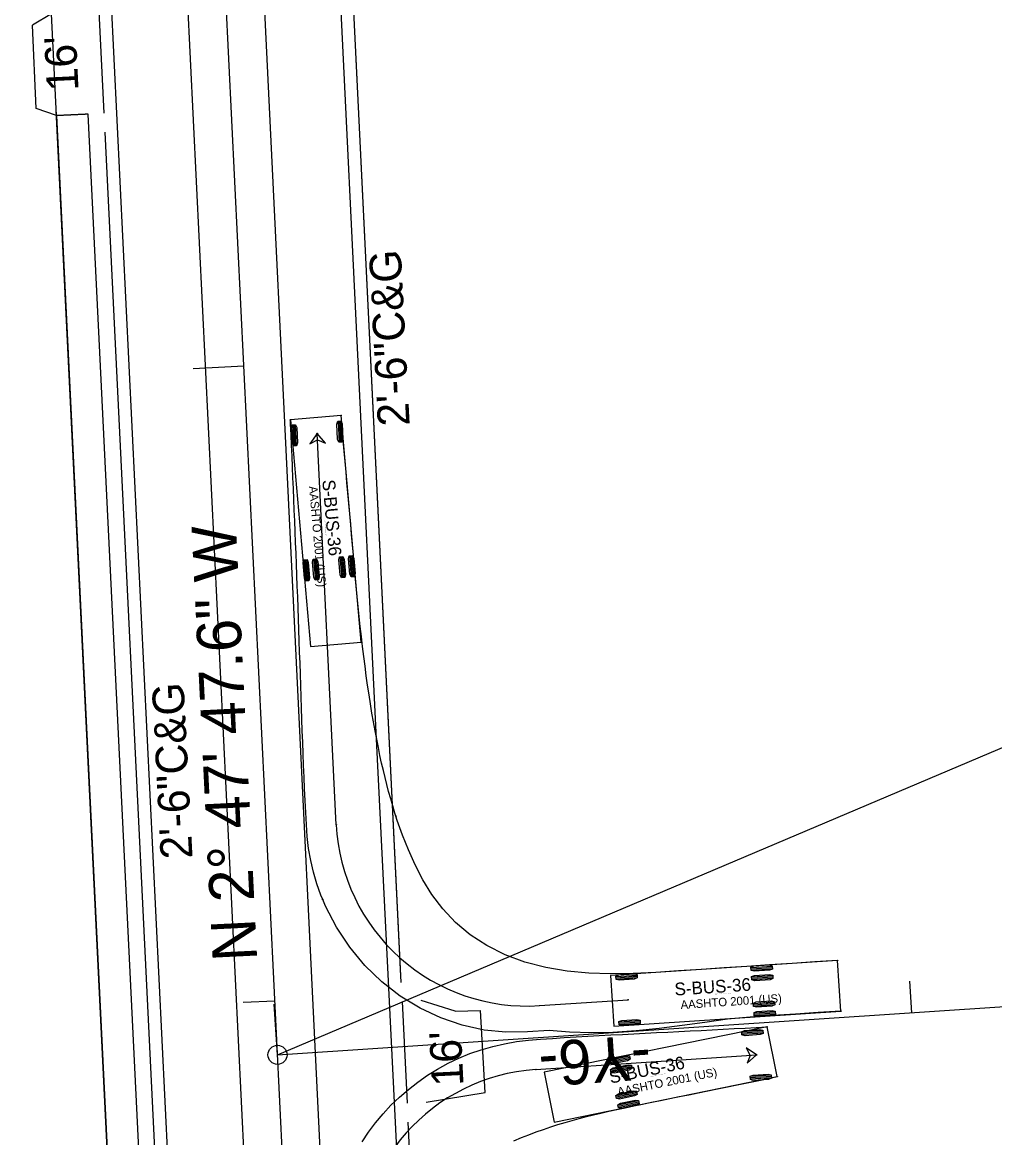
# Model space of a CAD drawing. Extents: x 2367848 to 2369479, y 800728 to 808616.
# Drawn here: x 2368775.2 to 2368928.2, y 804206 to 804381.5 of the extents above; entities that cross this region are included whole.
import ezdxf

# ---------------------------------------------------------------- set-up
doc = ezdxf.new("R2010")
doc.units = 0
for name, color, linetype in [('Prop AutoTurn Projected Path', 7, 'Continuous'), ('Prop AutoTurn Simulation', 7, 'Continuous'), ('Prop Conc 2ft 6in Curb and Gutter', 7, 'Continuous'), ('Prop Conc 4in Sidewalk', 7, 'Continuous'), ('Prop Conc Drive Radius Type', 7, 'Continuous'), ('Prop Conc Driveway', 7, 'Continuous'), ('Prop Dimension', 7, 'Continuous'), ('Prop EOT', 7, 'Continuous'), ('Prop Horizontal Alignment', 7, 'Continuous'), ('Prop Horizontal Alignment Direction Label', 7, 'Continuous'), ('Prop Horizontal Alignment Station Label', 7, 'Continuous'), ('Prop Horizontal Alignment Tick Large', 7, 'Continuous'), ('Prop Horizontal Alignment Tick Small', 7, 'Continuous'), ('Prop Lane Lines', 7, 'Continuous'), ('Prop Shade Light', 7, 'Continuous')]:
    doc.layers.add(name, color=color, linetype=linetype)

msp = doc.modelspace()

# ---------------------------------------------------------------- linework, layer by layer
at = {"layer": 'Prop AutoTurn Projected Path'}
for p, q in [((2368824.59, 804255.24), (2368821.59, 804316.8)), ((2368856.54, 804226.77), (2368870.5, 804227.69)), ((2368855.99, 804216.71), (2368890.72, 804219.01))]:
    msp.add_line(p, q, dxfattribs=at)
for centre, start, end in [((2368854.56, 804256.7), 182.7965, 273.7959), ((2368857.97, 804186.77), 93.7959, 182.7965)]:
    msp.add_arc(centre, 30, start, end, dxfattribs=at)
at = {"layer": 'Prop AutoTurn Simulation'}
for p, q in [((2368825.35, 804319.64), (2368817.38, 804318.94)), ((2368817.38, 804318.94), (2368820.52, 804283.28)), ((2368817.38, 804318.94), (2368817.38, 804318.94)), ((2368828.49, 804283.98), (2368825.35, 804319.64)), ((2368817.73, 804318.16), (2368817.89, 804314.83)), ((2368817.93, 804318.17), (2368818.1, 804314.84)), ((2368818.14, 804318.18), (2368818.3, 804314.85)), ((2368824.87, 804318.76), (2368825.03, 804315.43)), ((2368825.08, 804318.77), (2368825.24, 804315.44)), ((2368825.28, 804318.78), (2368825.45, 804315.45)), ((2368819.53, 804296.91), (2368819.82, 804293.59)), ((2368819.74, 804296.93), (2368820.03, 804293.61)), ((2368819.94, 804296.95), (2368820.24, 804293.63)), ((2368821.02, 804297.05), (2368821.32, 804293.72)), ((2368821.23, 804297.06), (2368821.52, 804293.74)), ((2368821.44, 804297.08), (2368821.73, 804293.76)), ((2368825.17, 804297.41), (2368825.47, 804294.09)), ((2368825.38, 804297.43), (2368825.67, 804294.11)), ((2368825.59, 804297.45), (2368825.88, 804294.13)), ((2368826.67, 804297.54), (2368826.96, 804294.22)), ((2368826.88, 804297.56), (2368827.17, 804294.24)), ((2368827.08, 804297.58), (2368827.38, 804294.26)), ((2368820.52, 804283.28), (2368828.49, 804283.98)), ((2368903.46, 804233.89), (2368867.74, 804231.52)), ((2368889.84, 804232.77), (2368893.16, 804232.99)), ((2368903.99, 804225.9), (2368903.46, 804233.89)), ((2368867.74, 804231.52), (2368868.27, 804223.53)), ((2368868.58, 804231.36), (2368871.91, 804231.58)), ((2368868.6, 804231.16), (2368871.92, 804231.38)), ((2368868.61, 804230.95), (2368871.94, 804231.17)), ((2368889.85, 804232.57), (2368893.18, 804232.79)), ((2368889.86, 804232.36), (2368893.19, 804232.58)), ((2368889.94, 804231.28), (2368893.26, 804231.5)), ((2368889.95, 804231.07), (2368893.28, 804231.29)), ((2368889.96, 804230.86), (2368893.29, 804231.08)), ((2368868.27, 804223.53), (2368903.99, 804225.9)), ((2368890.21, 804227.12), (2368893.54, 804227.34)), ((2368890.23, 804226.91), (2368893.55, 804227.13)), ((2368890.24, 804226.7), (2368893.57, 804226.92)), ((2368890.31, 804225.62), (2368893.64, 804225.84)), ((2368869.06, 804224.21), (2368872.38, 804224.43)), ((2368869.07, 804224.01), (2368872.4, 804224.23)), ((2368890.32, 804225.42), (2368893.65, 804225.64)), ((2368890.34, 804225.21), (2368893.66, 804225.43)), ((2368892.37, 804223.43), (2368857.29, 804216.28)), ((2368868.27, 804223.53), (2368868.27, 804223.53)), ((2368869.09, 804223.8), (2368872.41, 804224.02)), ((2368891.7, 804222.85), (2368888.38, 804222.62)), ((2368891.72, 804222.64), (2368888.39, 804222.41)), ((2368891.73, 804222.44), (2368888.41, 804222.21)), ((2368893.96, 804215.59), (2368892.37, 804223.43)), ((2368892.37, 804223.43), (2368892.37, 804223.43)), ((2368870.72, 804218.8), (2368867.45, 804218.14)), ((2368870.76, 804218.6), (2368867.5, 804217.94)), ((2368870.8, 804218.4), (2368867.54, 804217.73)), ((2368871.02, 804217.34), (2368867.75, 804216.67)), ((2368871.06, 804217.13), (2368867.79, 804216.47)), ((2368857.29, 804216.28), (2368858.88, 804208.44)), ((2368858.88, 804208.44), (2368893.96, 804215.59)), ((2368871.1, 804216.93), (2368867.84, 804216.26)), ((2368893.02, 804215.81), (2368889.7, 804215.59)), ((2368893.04, 804215.6), (2368889.71, 804215.39)), ((2368893.05, 804215.39), (2368889.72, 804215.18)), ((2368871.85, 804213.25), (2368868.59, 804212.59)), ((2368871.89, 804213.05), (2368868.63, 804212.38)), ((2368871.93, 804212.84), (2368868.67, 804212.18)), ((2368872.15, 804211.78), (2368868.88, 804211.12)), ((2368872.19, 804211.58), (2368868.93, 804210.91)), ((2368872.23, 804211.37), (2368868.97, 804210.71))]:
    msp.add_line(p, q, dxfattribs=at)
for points in [[(2368822.46, 804243.47), (2368822.19, 804244.17), (2368821.55, 804245.95), (2368821.02, 804247.77), (2368820.58, 804249.62), (2368820.25, 804251.49), (2368820.02, 804253.37), (2368819.89, 804255.27), (2368819.78, 804257.16), (2368819.68, 804259.03), (2368819.6, 804260.89), (2368819.52, 804262.74), (2368819.44, 804264.58), (2368819.38, 804266.4), (2368819.31, 804268.22), (2368819.25, 804270.02), (2368819.19, 804271.82), (2368819.13, 804273.6), (2368819.07, 804275.38), (2368819.01, 804277.15), (2368818.95, 804278.91), (2368818.89, 804280.66), (2368818.83, 804282.41), (2368818.77, 804284.15), (2368818.71, 804285.89), (2368818.65, 804287.62), (2368818.59, 804289.35), (2368818.53, 804291.07), (2368818.46, 804292.79), (2368818.4, 804294.51), (2368818.33, 804296.22), (2368818.27, 804297.93), (2368818.2, 804299.63), (2368818.13, 804301.34), (2368818.06, 804303.04), (2368817.99, 804304.74), (2368817.92, 804306.43), (2368817.85, 804308.13), (2368817.78, 804309.82), (2368817.71, 804311.51), (2368817.63, 804313.21), (2368817.56, 804314.89), (2368817.49, 804316.58), (2368817.41, 804318.27), (2368817.38, 804318.94)], [(2368833.97, 804256.59), (2368833.82, 804257.05), (2368833.47, 804258.19), (2368833.15, 804259.32), (2368832.83, 804260.44), (2368832.54, 804261.55), (2368832.26, 804262.66), (2368832, 804263.77), (2368831.73, 804264.92), (2368831.47, 804266.13), (2368831.21, 804267.39), (2368830.95, 804268.69), (2368830.7, 804270.02), (2368830.45, 804271.4), (2368830.21, 804272.8), (2368829.98, 804274.24), (2368829.75, 804275.69), (2368829.53, 804277.18), (2368829.32, 804278.68), (2368829.12, 804280.19), (2368828.92, 804281.73), (2368828.73, 804283.27), (2368828.55, 804284.83), (2368828.37, 804286.4), (2368828.2, 804287.99), (2368828.04, 804289.58), (2368827.88, 804291.17), (2368827.72, 804292.78), (2368827.58, 804294.39), (2368827.43, 804296.01), (2368827.29, 804297.63), (2368827.15, 804299.25), (2368827, 804300.88), (2368826.86, 804302.52), (2368826.71, 804304.15), (2368826.57, 804305.79), (2368826.43, 804307.44), (2368826.28, 804309.08), (2368826.14, 804310.73), (2368825.99, 804312.37), (2368825.85, 804314.02), (2368825.7, 804315.68), (2368825.55, 804317.33), (2368825.41, 804318.98), (2368825.35, 804319.64)], [(2368903.46, 804233.89), (2368899.89, 804233.65), (2368896.31, 804233.41), (2368892.74, 804233.18), (2368889.17, 804232.94), (2368885.6, 804232.7), (2368882.03, 804232.46), (2368878.45, 804232.23), (2368874.88, 804232), (2368871.31, 804231.82), (2368867.73, 804231.76), (2368867.73, 804231.76), (2368867.73, 804231.76), (2368864.32, 804231.87), (2368860.92, 804232.18), (2368857.57, 804232.75), (2368854.27, 804233.62), (2368851.15, 804234.78), (2368848.27, 804236.22), (2368845.65, 804237.92), (2368843.33, 804239.86), (2368841.33, 804241.99), (2368839.64, 804244.25), (2368838.21, 804246.58), (2368836.99, 804248.92), (2368835.93, 804251.27), (2368835, 804253.6), (2368834.19, 804255.91), (2368833.97, 804256.59)], [(2368903.99, 804225.9), (2368900.42, 804225.67), (2368896.84, 804225.43), (2368893.27, 804225.19), (2368889.7, 804224.96), (2368886.13, 804224.62), (2368882.57, 804224.13), (2368879, 804223.65), (2368875.39, 804223.15), (2368871.77, 804222.8), (2368868.12, 804222.53), (2368868.12, 804222.53), (2368864.67, 804222.48), (2368861.3, 804222.6), (2368858.06, 804222.86), (2368854.65, 804222.63), (2368851.27, 804222.58), (2368847.84, 804222.93), (2368844.41, 804223.69), (2368841.04, 804224.84), (2368837.78, 804226.38), (2368834.67, 804228.28), (2368831.76, 804230.53), (2368829.1, 804233.1), (2368826.71, 804235.97), (2368824.64, 804239.09), (2368822.91, 804242.43), (2368822.46, 804243.47)], [(2368828.68, 804205.31), (2368829.68, 804206.84), (2368830.77, 804208.31), (2368831.95, 804209.73), (2368833.2, 804211.08), (2368834.53, 804212.37), (2368835.93, 804213.59), (2368837.4, 804214.74), (2368838.94, 804215.81), (2368840.53, 804216.79), (2368842.18, 804217.69), (2368843.88, 804218.5), (2368845.62, 804219.21), (2368847.41, 804219.83), (2368849.23, 804220.36), (2368851.07, 804220.78), (2368852.94, 804221.11), (2368854.83, 804221.33), (2368856.72, 804221.47), (2368858.59, 804221.61), (2368860.46, 804221.73), (2368862.31, 804221.84), (2368864.15, 804221.95), (2368865.97, 804222.06), (2368867.79, 804222.15), (2368869.6, 804222.25), (2368871.39, 804222.34), (2368873.18, 804222.44), (2368874.96, 804222.53), (2368876.73, 804222.61), (2368878.49, 804222.7), (2368880.24, 804222.79), (2368881.99, 804222.88), (2368883.73, 804222.97), (2368885.47, 804223.06), (2368887.2, 804223.15), (2368888.93, 804223.24), (2368890.65, 804223.34), (2368892.37, 804223.43)], [(2368852.55, 804205.51), (2368853.72, 804206), (2368854.88, 804206.46), (2368856.03, 804206.89), (2368857.18, 804207.29), (2368858.32, 804207.67), (2368859.46, 804208.04), (2368860.59, 804208.38), (2368861.71, 804208.7), (2368862.82, 804209.01), (2368863.93, 804209.3), (2368865.05, 804209.58), (2368866.22, 804209.87), (2368867.45, 804210.15), (2368868.72, 804210.43), (2368870.03, 804210.71), (2368871.38, 804210.99), (2368872.77, 804211.27), (2368874.17, 804211.56), (2368875.61, 804211.85), (2368877.06, 804212.15), (2368878.54, 804212.45), (2368880.03, 804212.75), (2368881.53, 804213.06), (2368883.05, 804213.37), (2368884.58, 804213.68), (2368886.13, 804213.99), (2368887.68, 804214.31), (2368889.24, 804214.63), (2368890.81, 804214.95), (2368892.38, 804215.27), (2368893.96, 804215.59)]]:
    msp.add_lwpolyline(points, dxfattribs=at)
for points in [[(2368817.67, 804318.16), (2368818.19, 804318.18), (2368818.37, 804317.72), (2368818.49, 804315.33), (2368818.36, 804314.85), (2368817.84, 804314.83), (2368817.66, 804315.29), (2368817.54, 804317.68)], [(2368824.82, 804318.75), (2368825.33, 804318.78), (2368825.51, 804318.32), (2368825.63, 804315.92), (2368825.5, 804315.45), (2368824.98, 804315.42), (2368824.8, 804315.88), (2368824.68, 804318.28)], [(2368821.59, 804316.8), (2368820.45, 804315.16), (2368821.63, 804315.8), (2368822.88, 804315.28)], [(2368819.48, 804296.91), (2368820, 804296.95), (2368820.19, 804296.5), (2368820.4, 804294.11), (2368820.29, 804293.63), (2368819.77, 804293.59), (2368819.57, 804294.04), (2368819.36, 804296.43)], [(2368820.97, 804297.04), (2368821.49, 804297.09), (2368821.69, 804296.63), (2368821.9, 804294.24), (2368821.78, 804293.77), (2368821.26, 804293.72), (2368821.07, 804294.17), (2368820.86, 804296.56)], [(2368825.12, 804297.41), (2368825.64, 804297.45), (2368825.84, 804297), (2368826.05, 804294.61), (2368825.93, 804294.13), (2368825.42, 804294.09), (2368825.22, 804294.54), (2368825.01, 804296.93)], [(2368826.62, 804297.54), (2368827.14, 804297.58), (2368827.33, 804297.13), (2368827.54, 804294.74), (2368827.43, 804294.26), (2368826.91, 804294.22), (2368826.71, 804294.67), (2368826.5, 804297.06)], [(2368889.87, 804232.31), (2368889.83, 804232.83), (2368890.29, 804233.01), (2368892.68, 804233.17), (2368893.16, 804233.05), (2368893.19, 804232.53), (2368892.74, 804232.34), (2368890.34, 804232.18)], [(2368868.61, 804230.9), (2368868.58, 804231.42), (2368869.03, 804231.6), (2368871.43, 804231.76), (2368871.91, 804231.64), (2368871.94, 804231.12), (2368871.48, 804230.93), (2368869.09, 804230.77)], [(2368889.97, 804230.81), (2368889.93, 804231.33), (2368890.39, 804231.52), (2368892.78, 804231.67), (2368893.26, 804231.55), (2368893.29, 804231.03), (2368892.84, 804230.84), (2368890.44, 804230.68)], [(2368890.24, 804226.65), (2368890.21, 804227.17), (2368890.66, 804227.36), (2368893.06, 804227.52), (2368893.53, 804227.39), (2368893.57, 804226.87), (2368893.11, 804226.69), (2368890.72, 804226.53)], [(2368890.34, 804225.16), (2368890.31, 804225.67), (2368890.76, 804225.86), (2368893.16, 804226.02), (2368893.63, 804225.9), (2368893.67, 804225.38), (2368893.21, 804225.19), (2368890.82, 804225.03)], [(2368869.09, 804223.75), (2368869.05, 804224.26), (2368869.51, 804224.45), (2368871.9, 804224.61), (2368872.38, 804224.49), (2368872.41, 804223.97), (2368871.96, 804223.78), (2368869.56, 804223.62)], [(2368891.7, 804222.9), (2368891.73, 804222.38), (2368891.28, 804222.2), (2368888.89, 804222.03), (2368888.41, 804222.15), (2368888.37, 804222.67), (2368888.83, 804222.86), (2368891.22, 804223.03)], [(2368870.71, 804218.86), (2368870.81, 804218.35), (2368870.39, 804218.1), (2368868.04, 804217.62), (2368867.55, 804217.68), (2368867.44, 804218.19), (2368867.87, 804218.44), (2368870.22, 804218.92)], [(2368890.72, 804219.01), (2368889.05, 804220.12), (2368889.72, 804218.94), (2368889.21, 804217.69)], [(2368871.01, 804217.39), (2368871.11, 804216.88), (2368870.69, 804216.63), (2368868.34, 804216.15), (2368867.85, 804216.21), (2368867.74, 804216.72), (2368868.17, 804216.97), (2368870.52, 804217.45)], [(2368893.02, 804215.86), (2368893.05, 804215.34), (2368892.6, 804215.15), (2368890.2, 804215), (2368889.73, 804215.13), (2368889.69, 804215.65), (2368890.15, 804215.83), (2368892.54, 804215.98)], [(2368871.84, 804213.3), (2368871.95, 804212.79), (2368871.52, 804212.55), (2368869.17, 804212.07), (2368868.68, 804212.13), (2368868.58, 804212.64), (2368869, 804212.88), (2368871.35, 804213.36)], [(2368872.14, 804211.83), (2368872.24, 804211.32), (2368871.82, 804211.08), (2368869.47, 804210.6), (2368868.98, 804210.66), (2368868.87, 804211.17), (2368869.3, 804211.41), (2368871.65, 804211.89)]]:
    msp.add_lwpolyline(points, close=True, dxfattribs=at)
for centre in [(2368817.38, 804318.94), (2368825.35, 804319.64), (2368821.59, 804316.8), (2368833.97, 804256.59), (2368833.97, 804256.59), (2368824.59, 804255.24), (2368824.59, 804255.24), (2368822.46, 804243.47), (2368822.46, 804243.47), (2368903.46, 804233.89), (2368870.5, 804227.69), (2368856.54, 804226.77), (2368856.54, 804226.77), (2368903.99, 804225.9), (2368892.37, 804223.43), (2368890.72, 804219.01), (2368855.99, 804216.71), (2368855.99, 804216.71), (2368893.96, 804215.59)]:
    msp.add_circle(centre, 0.0417, dxfattribs=at)
at = {"layer": 'Prop Conc 2ft 6in Curb and Gutter'}
for p, q in [((2368834.77, 804231.4), (2368815.75, 804620.79)), ((2368834.82, 804230.42), (2368819.33, 804547.44)), ((2368800.46, 804113.82), (2368788.23, 804364.22)), ((2368836.87, 804188.32), (2368835.89, 804208.44))]:
    msp.add_line(p, q, dxfattribs=at)
at = {"layer": 'Prop Conc 4in Sidewalk'}
for p, q in [((2368792.97, 804113.45), (2368780.55, 804367.68)), ((2368797.97, 804113.7), (2368785.59, 804367.05))]:
    msp.add_line(p, q, dxfattribs=at)
msp.add_arc((2368785.22, 804364.06), 3.01, 83.0134, 92.5727, dxfattribs=at)
at = {"layer": 'Prop Conc Drive Radius Type'}
for p, q in [((2368788.09, 804367.21), (2368787.31, 804383.2)), ((2368834.96, 804227.42), (2368835.74, 804211.44))]:
    msp.add_line(p, q, dxfattribs=at)
at = {"layer": 'Prop Conc Driveway'}
for p, q in [((2368779.81, 804382.83), (2368776.81, 804381.04)), ((2368780.59, 804366.85), (2368779.81, 804382.83)), ((2368777.39, 804367.92), (2368776.81, 804381.04)), ((2368780.59, 804366.85), (2368777.39, 804367.92)), ((2368780.59, 804366.85), (2368785.09, 804367.07))]:
    msp.add_line(p, q, dxfattribs=at)
at = {"layer": 'Prop EOT'}
for p, q in [((2368830.84, 804270.86), (2368811.16, 804673.66)), ((2368802.46, 804113.92), (2368775.2, 804671.91)), ((2368856.01, 803755.6), (2368830.84, 804270.86)), ((2368843.28, 804225.91), (2368837.96, 804227.57)), ((2368843.28, 804225.91), (2368847.3, 804226.02)), ((2368847.99, 804213.12), (2368847.3, 804226.02)), ((2368838.74, 804211.58), (2368847.99, 804213.12))]:
    msp.add_line(p, q, dxfattribs=at)
at = {"layer": 'Prop Horizontal Alignment'}
for p, q in [((2368838.03, 803754.72), (2368793.18, 804672.79)), ((2368815.35, 804219.02), (2369078.59, 804236.49))]:
    msp.add_line(p, q, dxfattribs=at)
at = {"layer": 'Prop Horizontal Alignment Station Label'}
msp.add_line((2368815.35, 804219.02), (2368948.6, 804275.53), dxfattribs=at)
msp.add_circle((2368815.35, 804219.02), 1.5, dxfattribs=at)
at = {"layer": 'Prop Horizontal Alignment Tick Large'}
for p, q in [((2368810.06, 804327.37), (2368802.07, 804326.98)), ((2368810.06, 804327.37), (2368802.07, 804326.98)), ((2368815.35, 804219.02), (2368814.82, 804227))]:
    msp.add_line(p, q, dxfattribs=at)
at = {"layer": 'Prop Horizontal Alignment Tick Small'}
for p, q in [((2368915.13, 804225.64), (2368914.8, 804230.63)), ((2368814.94, 804227.49), (2368809.94, 804227.24)), ((2368814.94, 804227.49), (2368809.94, 804227.24))]:
    msp.add_line(p, q, dxfattribs=at)
at = {"layer": 'Prop Lane Lines'}
for p, q in [((2368832.04, 803754.43), (2368787.19, 804672.49)), ((2368844.02, 803755.01), (2368799.18, 804673.08))]:
    msp.add_line(p, q, dxfattribs=at)
at = {"layer": 'Prop Shade Light'}
for p, q in [((2368785.09, 804367.07), (2368780.59, 804366.85)), ((2368780.59, 804366.85), (2368792.97, 804113.45)), ((2368797.97, 804113.7), (2368785.59, 804367.05))]:
    msp.add_line(p, q, dxfattribs=at)
msp.add_lwpolyline([(2368780.59, 804366.85), (2368780.59, 804366.85)], dxfattribs=at)
msp.add_arc((2368785.22, 804364.06), 3.01, 83.0134, 92.5727, dxfattribs=at)

# ---------------------------------------------------------------- texts
at = {"layer": 'Prop AutoTurn Simulation'}
for s, height, rotation, p in [('AASHTO 2001 (US)', 1.3333, 275.0297, (2368820.3, 804308.47)), ('S-BUS-36', 2, 275.0297, (2368822.39, 804309.45)), ('(c) 2014 Transoft Solutions, Inc. All rights reserved.', 0.08, 275.0297, (2368822.75, 804303.08)), ('S-BUS-36', 2, 3.7959, (2368877.87, 804228.34)), ('AASHTO 2001 (US)', 1.3333, 3.7959, (2368878.8, 804226.23)), ('(c) 2014 Transoft Solutions, Inc. All rights reserved.', 0.08, 3.7959, (2368884.24, 804228.56)), ('S-BUS-36', 2, 11.5191, (2368867.75, 804214.49)), ('AASHTO 2001 (US)', 1.3333, 11.5191, (2368868.96, 804212.53)), ('(c) 2014 Transoft Solutions, Inc. All rights reserved.', 0.08, 11.5191, (2368874.04, 804215.57))]:
    msp.add_text(s, height=height, rotation=rotation, dxfattribs=at).set_placement(p)
at = {"layer": 'Prop Dimension'}
for s, rotation, p in [("16'", 92.7965, (2368784.06, 804370.77)), ('2\'-6"C&G', 92.9405, (2368836.15, 804318.07)), ('2\'-6"C&G', 92.9405, (2368801.99, 804249.96)), ("16'", 92.7965, (2368844.62, 804214.18))]:
    msp.add_text(s, height=5, rotation=rotation, dxfattribs=at).set_placement(p)
at = {"layer": 'Prop Horizontal Alignment Direction Label'}
msp.add_text('N 2%%d 47\' 47.6" W', height=7, rotation=92.7965, dxfattribs=at).set_placement((2368812.16, 804233.89))
at = {"layer": 'Prop Horizontal Alignment Station Label'}
msp.add_text('-Y6-', height=7, rotation=183.7959, dxfattribs=at).set_placement((2368873.87, 804222.18))

doc.saveas('drawing.dxf')
